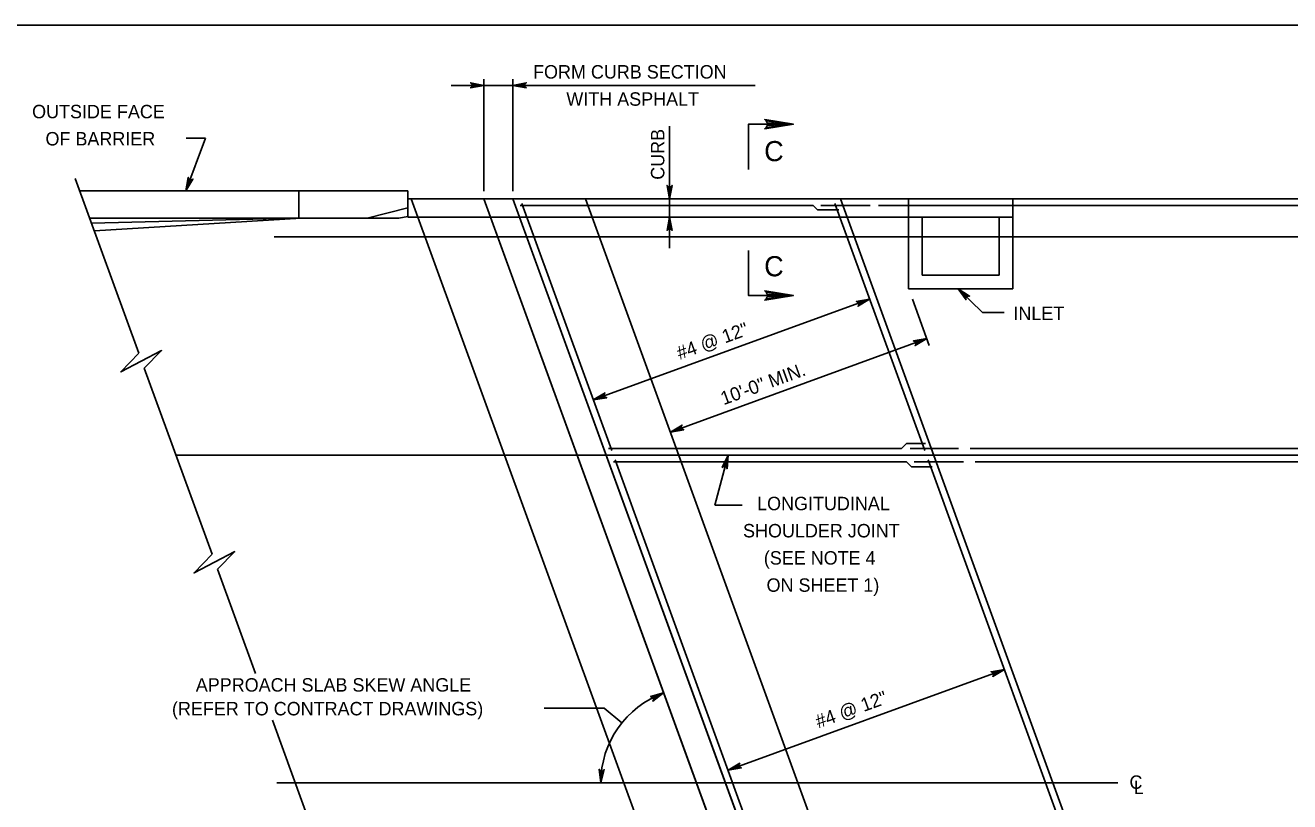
# Model space of a CAD drawing. Extents: x 2084213 to 2099800, y 976677 to 981262.
# Drawn here: x 2095426 to 2096353, y 978008 to 978577 of the extents above; entities that cross this region are included whole.
import ezdxf

# ---------------------------------------------------------------- set-up
doc = ezdxf.new("R2010")
doc.units = 0
doc.layers.add('1', color=7, linetype='Continuous')

msp = doc.modelspace()

# ---------------------------------------------------------------- linework, layer by layer
at = {"layer": '1'}
for p, q in [((2095738.29, 978532.86), (2095961.06, 978532.86)), ((2095762.3, 978455.21), (2095762.3, 978537.49)), ((2095783.59, 978455.21), (2095783.59, 978537.49)), ((2095898.4, 978413.49), (2095898.4, 978503.04)), ((2095558.39, 978494.04), (2095543.9, 978455.6)), ((2095544.24, 978494.04), (2095558.39, 978494.04)), ((2095509.48, 978336.5), (2095462.9, 978464.49)), ((2095466.14, 978455.6), (2095706.7, 978455.6)), ((2095626.7, 978435.6), (2095626.7, 978455.6)), ((2095706.7, 978436.73), (2095706.7, 978455.6)), ((2095706.7, 978436.35), (2095706.7, 978449.69)), ((2095706.7, 978449.69), (2096535.02, 978449.69)), ((2096015.68, 977607.34), (2095709.09, 978449.69)), ((2096068.89, 977607.34), (2095762.3, 978449.69)), ((2096090.17, 977607.34), (2095783.59, 978449.69)), ((2096143.38, 977607.34), (2095836.79, 978449.69)), ((2096330.17, 977607.34), (2096023.59, 978449.69)), ((2096073.59, 978436.35), (2096073.59, 978449.69)), ((2096149.9, 978383.85), (2096149.9, 978449.69)), ((2095676.7, 978435.6), (2095706.7, 978443.1)), ((2095788.95, 978444.69), (2096003.74, 978444.69)), ((2095856.06, 978265.18), (2095790.12, 978446.35)), ((2096006.77, 978441.65), (2096003.74, 978444.69)), ((2096006.77, 978441.65), (2096022.46, 978441.65)), ((2096009.37, 978444.69), (2096045.4, 978444.69)), ((2096085.42, 978265.18), (2096019.48, 978446.35)), ((2096051.65, 978444.69), (2096419.95, 978444.69)), ((2095473.42, 978435.6), (2095587.88, 978435.6)), ((2095473.42, 978435.6), (2095700.03, 978435.6)), ((2095474.82, 978431.75), (2095622.45, 978435.6)), ((2095476.84, 978426.2), (2095628.41, 978435.6)), ((2095700.03, 978435.6), (2095706.7, 978436.73)), ((2095706.7, 978436.35), (2096149.9, 978436.35)), ((2096073.59, 978383.85), (2096073.59, 978436.35)), ((2096083.59, 978393.85), (2096083.59, 978436.35)), ((2096139.9, 978393.85), (2096139.9, 978436.35)), ((2095608.73, 978421.85), (2096410.28, 978421.85)), ((2096083.59, 978393.85), (2096139.9, 978393.85)), ((2096073.59, 978383.85), (2096149.9, 978383.85)), ((2096127.8, 978366.32), (2096109.92, 978383.85)), ((2096045.05, 978376.09), (2095842.52, 978302.37)), ((2096088.73, 978342.25), (2096076.42, 978376.08)), ((2096127.8, 978366.32), (2096143.7, 978366.32)), ((2095898.98, 978278.83), (2096086.92, 978347.24)), ((2095563.08, 978189.24), (2095513.43, 978325.66)), ((2095853.68, 978266.85), (2096068.47, 978266.85)), ((2096072.1, 978270.48), (2096068.47, 978266.85)), ((2096072.1, 978270.48), (2096085.98, 978270.48)), ((2096074.62, 978266.85), (2096110.13, 978266.85)), ((2096118.73, 978266.85), (2096420.56, 978266.85)), ((2095536.66, 978261.85), (2096535.02, 978261.85)), ((2095857.32, 978256.85), (2096072.11, 978256.85)), ((2096030.77, 977785.18), (2095858.49, 978258.52)), ((2095931.61, 978225.32), (2095941.34, 978261.85)), ((2096075.74, 978253.22), (2096072.11, 978256.85)), ((2096077.68, 978256.85), (2096113.77, 978256.85)), ((2096260.12, 977785.18), (2096087.84, 978258.52)), ((2096122.42, 978256.85), (2096420.56, 978256.85)), ((2096075.74, 978253.22), (2096090.83, 978253.22)), ((2095931.61, 978225.32), (2095951.6, 978225.32)), ((2095594.87, 978101.9), (2095567.03, 978178.4)), ((2096143.81, 978104.76), (2095941.28, 978031.04)), ((2095806.62, 978076.39), (2095850.42, 978076.39)), ((2095863.54, 978065.81), (2095850.42, 978076.39)), ((2095671.46, 977891.47), (2095607.35, 978067.63)), ((2095610.6, 978021.85), (2096227.02, 978021.85))]:
    msp.add_line(p, q, dxfattribs=at)
for points in [[(2096781.61, 976726.46), (2096781.61, 978576.86), (2094202.86, 978576.86), (2094202.86, 976726.46), (2096781.61, 976726.46), (2096781.61, 976812.94), (2096125.44, 976812.94), (2096125.44, 977025.14), (2096781.61, 977025.14), (2096781.61, 977120.16), (2096125.44, 977120.16), (2096125.44, 976726.46), (2096383.97, 976726.46), (2096383.97, 976812.94), (2096383.97, 976726.46), (2096636.6, 976726.46), (2096636.6, 976812.94), (2096636.6, 976772.54), (2096781.61, 976772.54)], [(2095762.3, 978532.86), (2095752.52, 978531.03), (2095752.89, 978531.29), (2095753.27, 978531.55), (2095753.46, 978531.88), (2095753.66, 978532.21), (2095753.72, 978532.53), (2095753.77, 978532.86), (2095753.72, 978533.19), (2095753.66, 978533.52), (2095753.46, 978533.85), (2095753.27, 978534.17), (2095752.89, 978534.44), (2095752.52, 978534.7), (2095762.3, 978532.86), (2095752.89, 978534.44), (2095753.27, 978534.17), (2095762.3, 978532.86), (2095753.46, 978533.85), (2095753.66, 978533.52), (2095762.3, 978532.86), (2095753.72, 978533.19), (2095753.77, 978532.86), (2095762.3, 978532.86), (2095753.72, 978532.53), (2095753.66, 978532.21), (2095762.3, 978532.86), (2095753.46, 978531.88), (2095753.27, 978531.55), (2095762.3, 978532.86), (2095752.89, 978531.29)], [(2095783.59, 978532.86), (2095793.37, 978534.7), (2095792.99, 978534.44), (2095792.62, 978534.17), (2095792.42, 978533.85), (2095792.23, 978533.52), (2095792.17, 978533.19), (2095792.12, 978532.86), (2095792.17, 978532.53), (2095792.23, 978532.21), (2095792.42, 978531.88), (2095792.62, 978531.55), (2095792.99, 978531.29), (2095793.37, 978531.03), (2095783.59, 978532.86), (2095792.99, 978531.29), (2095792.62, 978531.55), (2095783.59, 978532.86), (2095792.42, 978531.88), (2095792.23, 978532.21), (2095783.59, 978532.86), (2095792.17, 978532.53), (2095792.12, 978532.86), (2095783.59, 978532.86), (2095792.17, 978533.19), (2095792.23, 978533.52), (2095783.59, 978532.86), (2095792.42, 978533.85), (2095792.62, 978534.17), (2095783.59, 978532.86), (2095792.99, 978534.44)], [(2095956.15, 978471.28), (2095956.15, 978504.35), (2095989.22, 978504.35)], [(2095969.2, 978506.86), (2095969.95, 978505.41), (2095989.22, 978504.35), (2095969.2, 978506.86), (2095968.18, 978507.74), (2095989.22, 978504.35), (2095969.96, 978503.39), (2095969.26, 978501.96), (2095989.22, 978504.35), (2095968.18, 978501), (2095969.26, 978501.96)], [(2095543.9, 978455.6), (2095549.07, 978464.11), (2095548.69, 978463.85), (2095548.31, 978463.59), (2095547.94, 978463.52), (2095547.56, 978463.45), (2095547.23, 978463.52), (2095546.91, 978463.58), (2095546.62, 978463.75), (2095546.33, 978463.92), (2095546.09, 978464.22), (2095545.85, 978464.51), (2095545.74, 978464.96), (2095545.63, 978465.4), (2095543.9, 978455.6), (2095545.74, 978464.96), (2095545.85, 978464.51), (2095543.9, 978455.6), (2095546.09, 978464.22), (2095546.33, 978463.92), (2095543.9, 978455.6), (2095546.62, 978463.75), (2095546.91, 978463.58), (2095543.9, 978455.6), (2095547.23, 978463.52), (2095547.56, 978463.45), (2095543.9, 978455.6), (2095547.94, 978463.52), (2095548.31, 978463.59), (2095543.9, 978455.6), (2095548.69, 978463.85)], [(2095898.4, 978449.69), (2095896.57, 978459.47), (2095896.83, 978459.09), (2095897.09, 978458.72), (2095897.42, 978458.52), (2095897.75, 978458.33), (2095898.07, 978458.27), (2095898.4, 978458.22), (2095898.73, 978458.27), (2095899.06, 978458.33), (2095899.39, 978458.52), (2095899.71, 978458.72), (2095899.98, 978459.09), (2095900.24, 978459.47), (2095898.4, 978449.69), (2095899.98, 978459.09), (2095899.71, 978458.72), (2095898.4, 978449.69), (2095899.39, 978458.52), (2095899.06, 978458.33), (2095898.4, 978449.69), (2095898.73, 978458.27), (2095898.4, 978458.22), (2095898.4, 978449.69), (2095898.07, 978458.27), (2095897.75, 978458.33), (2095898.4, 978449.69), (2095897.42, 978458.52), (2095897.09, 978458.72), (2095898.4, 978449.69), (2095896.83, 978459.09)], [(2095898.4, 978436.35), (2095900.24, 978426.57), (2095899.98, 978426.94), (2095899.71, 978427.32), (2095899.39, 978427.51), (2095899.06, 978427.71), (2095898.73, 978427.77), (2095898.4, 978427.82), (2095898.07, 978427.77), (2095897.75, 978427.71), (2095897.42, 978427.51), (2095897.09, 978427.32), (2095896.83, 978426.94), (2095896.57, 978426.57), (2095898.4, 978436.35), (2095896.83, 978426.94), (2095897.09, 978427.32), (2095898.4, 978436.35), (2095897.42, 978427.51), (2095897.75, 978427.71), (2095898.4, 978436.35), (2095898.07, 978427.77), (2095898.4, 978427.82), (2095898.4, 978436.35), (2095898.73, 978427.77), (2095899.06, 978427.71), (2095898.4, 978436.35), (2095899.39, 978427.51), (2095899.71, 978427.32), (2095898.4, 978436.35), (2095899.98, 978426.94)], [(2095956.15, 978411.93), (2095956.15, 978378.86), (2095989.22, 978378.86)], [(2096109.92, 978383.85), (2096118.26, 978378.41), (2096117.81, 978378.48), (2096117.36, 978378.55), (2096116.99, 978378.45), (2096116.62, 978378.35), (2096116.35, 978378.15), (2096116.09, 978377.95), (2096115.9, 978377.68), (2096115.71, 978377.4), (2096115.63, 978377.03), (2096115.54, 978376.66), (2096115.63, 978376.21), (2096115.72, 978375.76), (2096109.92, 978383.85), (2096115.63, 978376.21), (2096115.54, 978376.66), (2096109.92, 978383.85), (2096115.63, 978377.03), (2096115.71, 978377.4), (2096109.92, 978383.85), (2096115.9, 978377.68), (2096116.09, 978377.95), (2096109.92, 978383.85), (2096116.35, 978378.15), (2096116.62, 978378.35), (2096109.92, 978383.85), (2096116.99, 978378.45), (2096117.36, 978378.55), (2096109.92, 978383.85), (2096117.81, 978378.48)], [(2095969.2, 978376.35), (2095969.95, 978377.79), (2095989.22, 978378.86), (2095969.2, 978376.35), (2095968.18, 978375.47), (2095989.22, 978378.86), (2095969.96, 978379.81), (2095969.26, 978381.25), (2095989.22, 978378.86), (2095968.18, 978382.2), (2095969.26, 978381.25)], [(2096045.05, 978376.09), (2096036.48, 978371.02), (2096036.75, 978371.39), (2096037.01, 978371.76), (2096037.08, 978372.14), (2096037.16, 978372.51), (2096037.1, 978372.84), (2096037.04, 978373.17), (2096036.87, 978373.46), (2096036.71, 978373.75), (2096036.41, 978373.99), (2096036.12, 978374.23), (2096035.67, 978374.35), (2096035.23, 978374.46), (2096045.05, 978376.09), (2096035.67, 978374.35), (2096036.12, 978374.23), (2096045.05, 978376.09), (2096036.41, 978373.99), (2096036.71, 978373.75), (2096045.05, 978376.09), (2096036.87, 978373.46), (2096037.04, 978373.17), (2096045.05, 978376.09), (2096037.1, 978372.84), (2096037.16, 978372.51), (2096045.05, 978376.09), (2096037.08, 978372.14), (2096037.01, 978371.76), (2096045.05, 978376.09), (2096036.75, 978371.39)], [(2096086.92, 978347.24), (2096078.35, 978342.17), (2096078.61, 978342.54), (2096078.88, 978342.92), (2096078.95, 978343.29), (2096079.02, 978343.67), (2096078.96, 978343.99), (2096078.9, 978344.32), (2096078.74, 978344.61), (2096078.57, 978344.9), (2096078.28, 978345.14), (2096077.98, 978345.38), (2096077.54, 978345.5), (2096077.09, 978345.62), (2096086.92, 978347.24), (2096077.54, 978345.5), (2096077.98, 978345.38), (2096086.92, 978347.24), (2096078.28, 978345.14), (2096078.57, 978344.9), (2096086.92, 978347.24), (2096078.74, 978344.61), (2096078.9, 978344.32), (2096086.92, 978347.24), (2096078.96, 978343.99), (2096079.02, 978343.67), (2096086.92, 978347.24), (2096078.95, 978343.29), (2096078.88, 978342.92), (2096086.92, 978347.24), (2096078.61, 978342.54)], [(2095509.48, 978336.5), (2095496.32, 978322.88), (2095526.09, 978338.48), (2095513.41, 978325.65)], [(2095842.52, 978302.37), (2095851.09, 978307.44), (2095850.83, 978307.07), (2095850.56, 978306.69), (2095850.49, 978306.32), (2095850.42, 978305.94), (2095850.48, 978305.62), (2095850.54, 978305.29), (2095850.7, 978305), (2095850.87, 978304.71), (2095851.16, 978304.47), (2095851.46, 978304.23), (2095851.9, 978304.11), (2095852.35, 978303.99), (2095842.52, 978302.37), (2095851.9, 978304.11), (2095851.46, 978304.23), (2095842.52, 978302.37), (2095851.16, 978304.47), (2095850.87, 978304.71), (2095842.52, 978302.37), (2095850.7, 978305), (2095850.54, 978305.29), (2095842.52, 978302.37), (2095850.48, 978305.62), (2095850.42, 978305.94), (2095842.52, 978302.37), (2095850.49, 978306.32), (2095850.56, 978306.69), (2095842.52, 978302.37), (2095850.83, 978307.07)], [(2095898.98, 978278.83), (2095907.55, 978283.9), (2095907.28, 978283.53), (2095907.02, 978283.16), (2095906.95, 978282.78), (2095906.88, 978282.41), (2095906.94, 978282.08), (2095906.99, 978281.75), (2095907.16, 978281.46), (2095907.33, 978281.17), (2095907.62, 978280.93), (2095907.91, 978280.69), (2095908.36, 978280.57), (2095908.8, 978280.46), (2095898.98, 978278.83), (2095908.36, 978280.57), (2095907.91, 978280.69), (2095898.98, 978278.83), (2095907.62, 978280.93), (2095907.33, 978281.17), (2095898.98, 978278.83), (2095907.16, 978281.46), (2095906.99, 978281.75), (2095898.98, 978278.83), (2095906.94, 978282.08), (2095906.88, 978282.41), (2095898.98, 978278.83), (2095906.95, 978282.78), (2095907.02, 978283.16), (2095898.98, 978278.83), (2095907.28, 978283.53)], [(2095941.34, 978261.85), (2095940.59, 978251.92), (2095940.44, 978252.35), (2095940.28, 978252.78), (2095940.01, 978253.06), (2095939.75, 978253.33), (2095939.45, 978253.47), (2095939.14, 978253.61), (2095938.81, 978253.64), (2095938.48, 978253.67), (2095938.11, 978253.56), (2095937.75, 978253.46), (2095937.4, 978253.16), (2095937.05, 978252.87), (2095941.34, 978261.85), (2095937.4, 978253.16), (2095937.75, 978253.46), (2095941.34, 978261.85), (2095938.11, 978253.56), (2095938.48, 978253.67), (2095941.34, 978261.85), (2095938.81, 978253.64), (2095939.14, 978253.61), (2095941.34, 978261.85), (2095939.45, 978253.47), (2095939.75, 978253.33), (2095941.34, 978261.85), (2095940.01, 978253.06), (2095940.28, 978252.78), (2095941.34, 978261.85), (2095940.44, 978252.35)], [(2095563.08, 978189.24), (2095549.92, 978175.62), (2095579.69, 978191.21), (2095567.01, 978178.39)], [(2096143.81, 978104.76), (2096135.24, 978099.69), (2096135.5, 978100.06), (2096135.77, 978100.44), (2096135.84, 978100.81), (2096135.91, 978101.19), (2096135.85, 978101.51), (2096135.79, 978101.84), (2096135.63, 978102.13), (2096135.46, 978102.42), (2096135.17, 978102.66), (2096134.87, 978102.9), (2096134.43, 978103.02), (2096133.98, 978103.14), (2096143.81, 978104.76), (2096134.43, 978103.02), (2096134.87, 978102.9), (2096143.81, 978104.76), (2096135.17, 978102.66), (2096135.46, 978102.42), (2096143.81, 978104.76), (2096135.63, 978102.13), (2096135.79, 978101.84), (2096143.81, 978104.76), (2096135.85, 978101.51), (2096135.91, 978101.19), (2096143.81, 978104.76), (2096135.84, 978100.81), (2096135.77, 978100.44), (2096143.81, 978104.76), (2096135.5, 978100.06)], [(2095894.08, 978087.63), (2095886.11, 978081.66), (2095886.33, 978082.06), (2095886.56, 978082.46), (2095886.59, 978082.84), (2095886.62, 978083.22), (2095886.52, 978083.54), (2095886.43, 978083.86), (2095886.23, 978084.13), (2095886.04, 978084.4), (2095885.72, 978084.61), (2095885.4, 978084.82), (2095884.94, 978084.88), (2095884.49, 978084.95), (2095894.08, 978087.63), (2095884.94, 978084.88), (2095885.4, 978084.82), (2095894.08, 978087.63), (2095885.72, 978084.61), (2095886.04, 978084.4), (2095894.08, 978087.63), (2095886.23, 978084.13), (2095886.43, 978083.86), (2095894.08, 978087.63), (2095886.52, 978083.54), (2095886.62, 978083.22), (2095894.08, 978087.63), (2095886.59, 978082.84), (2095886.56, 978082.46), (2095894.08, 978087.63), (2095886.33, 978082.06)], [(2095848.02, 978021.85), (2095846.9, 978031.74), (2095847.13, 978031.35), (2095847.37, 978030.95), (2095847.68, 978030.73), (2095847.99, 978030.52), (2095848.32, 978030.44), (2095848.64, 978030.36), (2095848.97, 978030.39), (2095849.3, 978030.42), (2095849.64, 978030.59), (2095849.98, 978030.76), (2095850.27, 978031.12), (2095850.56, 978031.48), (2095848.02, 978021.85), (2095850.27, 978031.12), (2095849.98, 978030.76), (2095848.02, 978021.85), (2095849.64, 978030.59), (2095849.3, 978030.42), (2095848.02, 978021.85), (2095848.97, 978030.39), (2095848.64, 978030.36), (2095848.02, 978021.85), (2095848.32, 978030.44), (2095847.99, 978030.52), (2095848.02, 978021.85), (2095847.68, 978030.73), (2095847.37, 978030.95), (2095848.02, 978021.85), (2095847.13, 978031.35)], [(2095941.28, 978031.04), (2095949.85, 978036.11), (2095949.58, 978035.74), (2095949.32, 978035.37), (2095949.25, 978034.99), (2095949.18, 978034.62), (2095949.24, 978034.29), (2095949.3, 978033.96), (2095949.46, 978033.67), (2095949.63, 978033.38), (2095949.92, 978033.14), (2095950.21, 978032.9), (2095950.66, 978032.78), (2095951.1, 978032.67), (2095941.28, 978031.04), (2095950.66, 978032.78), (2095950.21, 978032.9), (2095941.28, 978031.04), (2095949.92, 978033.14), (2095949.63, 978033.38), (2095941.28, 978031.04), (2095949.46, 978033.67), (2095949.3, 978033.96), (2095941.28, 978031.04), (2095949.24, 978034.29), (2095949.18, 978034.62), (2095941.28, 978031.04), (2095949.25, 978034.99), (2095949.32, 978035.37), (2095941.28, 978031.04), (2095949.58, 978035.74)]]:
    msp.add_lwpolyline(points, dxfattribs=at)
msp.add_lwpolyline([(2095762.3, 978449.69), (2095783.59, 978449.69), (2096090.17, 977607.34), (2096068.89, 977607.34)], close=True, dxfattribs=at)
msp.add_arc((2095918.02, 978021.85), 70, 110, 180, dxfattribs=at)

# ---------------------------------------------------------------- texts
for s, height, p in [('FORM CURB SECTION', 9.8425, (2095798.35, 978537.83)), ('WITH ASPHALT', 9.8425, (2095822.76, 978517.91)), ('OUTSIDE FACE', 9.8425, (2095431.22, 978508.72)), ('OF BARRIER', 9.843, (2095441.02, 978488.8)), ('C', 14.76, (2095967.76, 978477.27)), ('C', 14.76, (2095967.76, 978392.93)), ('INLET', 9.843, (2096150.39, 978360.89)), ('LONGITUDINAL', 9.8425, (2095962.55, 978221.51)), ('SHOULDER JOINT', 9.8425, (2095952.25, 978201.59)), ('(SEE NOTE 4', 9.8425, (2095967.47, 978181.67)), ('ON SHEET 1)', 9.8425, (2095969.49, 978161.74)), ('APPROACH SLAB SKEW ANGLE', 9.8425, (2095551.16, 978088.6)), ('(REFER TO CONTRACT DRAWINGS)', 9.8425, (2095533.73, 978071.19)), ('C', 9.84, (2096235.45, 978017.35)), ('L', 9.84, (2096238.61, 978013.57))]:
    msp.add_text(s, height=height, dxfattribs=at).set_placement(p)
for s, height, rotation, p in [('CURB', 9.843, 90, (2095894.59, 978463.65)), ('#4 @ 12"', 9.843, 20, (2095905.79, 978331.61)), ('10\'-0" MIN.', 9.8425, 20, (2095937.99, 978298.41)), ('#4 @ 12"', 9.843, 20, (2096007.5, 978061.57))]:
    msp.add_text(s, height=height, rotation=rotation, dxfattribs=at).set_placement(p)

doc.saveas('drawing.dxf')
